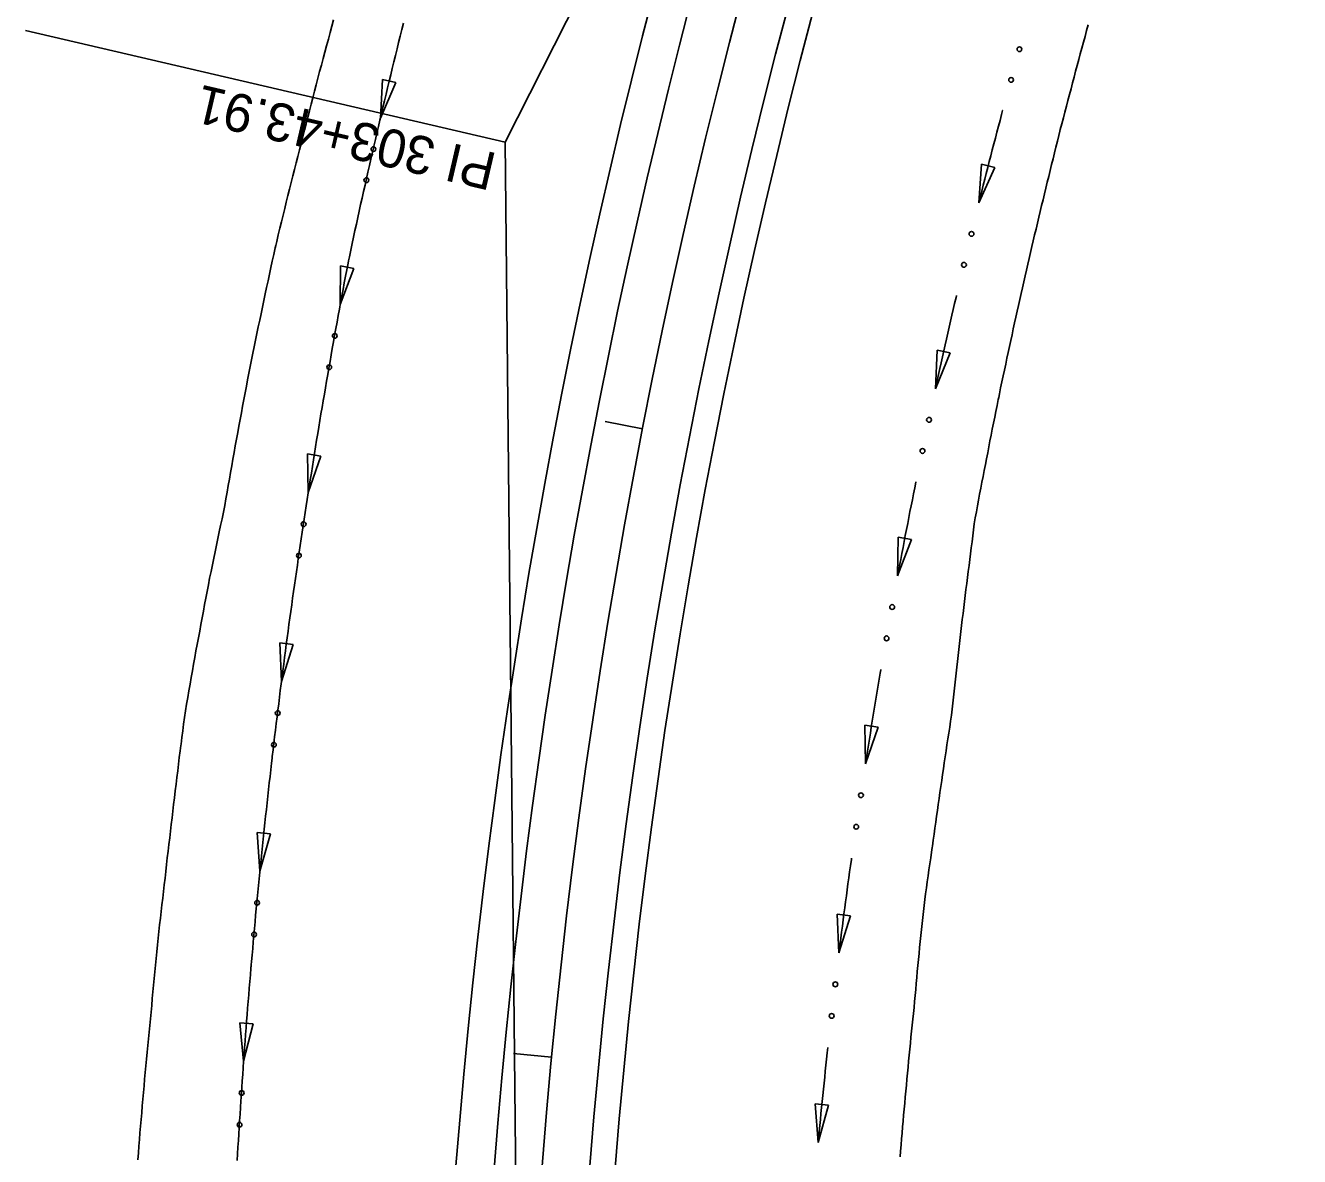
# Model space of a CAD drawing. Extents: x 1611108 to 1749517, y 619561 to 797725.
# Drawn here: x 1713039.8 to 1713240.2, y 759440 to 759618.1 of the extents above; entities that cross this region are included whole.
import ezdxf

# ---------------------------------------------------------------- set-up
doc = ezdxf.new("R2010")
doc.units = 0
for name, color, linetype in [('R_Ditch', 7, 'Continuous'), ('R_Horz Alg', 7, 'Continuous'), ('R_Horz Alg Annot', 7, 'Continuous'), ('R_Horz Alg Stationing', 7, 'Continuous'), ('R_Proposed Const Limits', 7, 'Continuous'), ('R_Proposed Road', 7, 'Continuous'), ('R_Proposed_SHLDR', 7, 'Continuous')]:
    doc.layers.add(name, color=color, linetype=linetype)

msp = doc.modelspace()

# ---------------------------------------------------------------- linework, layer by layer
at = {"layer": 'R_Ditch'}
for p, q in [((1713095.96, 759609.57), (1713095.6, 759603.48)), ((1713095.6, 759603.48), (1713098.02, 759609.08)), ((1713098.02, 759609.08), (1713095.96, 759609.57)), ((1713190.21, 759596.2), (1713189.76, 759590.12)), ((1713192.26, 759595.68), (1713190.21, 759596.2)), ((1713189.76, 759590.12), (1713192.26, 759595.68)), ((1713089.35, 759580.21), (1713089.29, 759574.12)), ((1713091.43, 759579.82), (1713089.35, 759580.21)), ((1713089.29, 759574.12), (1713091.43, 759579.82)), ((1713183.2, 759566.96), (1713182.94, 759560.87)), ((1713182.94, 759560.87), (1713185.26, 759566.5)), ((1713185.26, 759566.5), (1713183.2, 759566.96)), ((1713086.24, 759550.27), (1713084.15, 759550.6)), ((1713084.15, 759550.6), (1713084.25, 759544.51)), ((1713084.25, 759544.51), (1713086.24, 759550.27)), ((1713177.07, 759537.52), (1713176.99, 759531.43)), ((1713176.99, 759531.43), (1713179.15, 759537.13)), ((1713179.15, 759537.13), (1713177.07, 759537.52)), ((1713081.86, 759520.58), (1713079.76, 759520.86)), ((1713079.76, 759520.86), (1713080.04, 759514.77)), ((1713080.04, 759514.77), (1713081.86, 759520.58)), ((1713173.92, 759507.58), (1713171.83, 759507.91)), ((1713171.83, 759507.91), (1713171.93, 759501.82)), ((1713171.93, 759501.82), (1713173.92, 759507.58)), ((1713078.31, 759490.78), (1713076.2, 759491)), ((1713076.2, 759491), (1713076.65, 759484.92)), ((1713076.65, 759484.92), (1713078.31, 759490.78)), ((1713169.57, 759477.89), (1713167.47, 759478.16)), ((1713167.47, 759478.16), (1713167.76, 759472.08)), ((1713167.76, 759472.08), (1713169.57, 759477.89)), ((1713075.58, 759460.9), (1713073.47, 759461.06)), ((1713073.47, 759461.06), (1713074.08, 759455)), ((1713074.08, 759455), (1713075.58, 759460.9)), ((1713166.12, 759448.09), (1713164.01, 759448.29)), ((1713164.01, 759448.29), (1713164.48, 759442.22)), ((1713164.48, 759442.22), (1713166.12, 759448.09))]:
    msp.add_line(p, q, dxfattribs=at)
for points in [[(1713073.08, 759439.36), (1713073.14, 759440.4), (1713073.2, 759441.45), (1713073.26, 759442.49), (1713073.33, 759443.53), (1713073.39, 759444.58), (1713073.46, 759445.62), (1713073.52, 759446.67), (1713073.59, 759447.71), (1713073.66, 759448.76), (1713073.73, 759449.8), (1713073.8, 759450.84), (1713073.87, 759451.89), (1713073.94, 759452.93), (1713074.01, 759453.98), (1713074.09, 759455.02), (1713074.16, 759456.06), (1713074.24, 759457.11), (1713074.32, 759458.15), (1713074.4, 759459.19), (1713074.48, 759460.24), (1713074.56, 759461.28), (1713074.64, 759462.32), (1713074.72, 759463.37), (1713074.8, 759464.41), (1713074.89, 759465.45), (1713074.97, 759466.5), (1713075.06, 759467.54), (1713075.15, 759468.58), (1713075.24, 759469.63), (1713075.33, 759470.67), (1713075.42, 759471.71), (1713075.51, 759472.75), (1713075.6, 759473.8), (1713075.69, 759474.84), (1713075.79, 759475.88), (1713075.88, 759476.93), (1713075.98, 759477.97), (1713076.08, 759479.01), (1713076.18, 759480.05), (1713076.28, 759481.09), (1713076.38, 759482.14), (1713076.48, 759483.18), (1713076.58, 759484.22), (1713076.68, 759485.26), (1713076.79, 759486.3), (1713076.89, 759487.35), (1713077, 759488.39), (1713077.11, 759489.43), (1713077.22, 759490.47), (1713077.33, 759491.51), (1713077.44, 759492.55), (1713077.55, 759493.59), (1713077.66, 759494.64), (1713077.77, 759495.68), (1713077.89, 759496.72), (1713078, 759497.76), (1713078.12, 759498.8), (1713078.24, 759499.84), (1713078.36, 759500.88), (1713078.48, 759501.92), (1713078.57, 759502.73), (1713078.6, 759502.96), (1713078.72, 759504), (1713078.84, 759505.04), (1713078.97, 759506.08), (1713079.09, 759507.12), (1713079.22, 759508.16), (1713079.34, 759509.2), (1713079.47, 759510.24), (1713079.6, 759511.28), (1713079.73, 759512.32), (1713079.86, 759513.36), (1713079.99, 759514.4), (1713080.13, 759515.44), (1713080.26, 759516.48), (1713080.39, 759517.51), (1713080.53, 759518.55), (1713080.67, 759519.59), (1713080.8, 759520.63), (1713080.94, 759521.67), (1713081.08, 759522.71), (1713081.22, 759523.75), (1713081.37, 759524.78), (1713081.51, 759525.82), (1713081.65, 759526.86), (1713081.8, 759527.9), (1713081.94, 759528.93), (1713082.09, 759529.97), (1713082.24, 759531.01), (1713082.39, 759532.05), (1713082.54, 759533.08), (1713082.69, 759534.12), (1713082.84, 759535.16), (1713082.99, 759536.19), (1713083.15, 759537.23), (1713083.3, 759538.27), (1713083.46, 759539.3), (1713083.61, 759540.34), (1713083.77, 759541.38), (1713083.93, 759542.41), (1713084.09, 759543.45), (1713084.25, 759544.48), (1713084.41, 759545.52), (1713084.58, 759546.55), (1713084.74, 759547.59), (1713084.91, 759548.62), (1713085.07, 759549.66), (1713085.24, 759550.69), (1713085.41, 759551.73), (1713085.57, 759552.76), (1713085.74, 759553.8), (1713085.92, 759554.83), (1713086.09, 759555.87), (1713086.26, 759556.9), (1713086.43, 759557.93), (1713086.61, 759558.97), (1713086.79, 759560), (1713086.96, 759561.03), (1713087.14, 759562.07), (1713087.32, 759563.1), (1713087.5, 759564.13), (1713087.68, 759565.17), (1713087.86, 759566.2), (1713088.04, 759567.23), (1713088.23, 759568.26), (1713088.41, 759569.29), (1713088.6, 759570.33), (1713088.79, 759571.36), (1713088.97, 759572.39), (1713089.16, 759573.42), (1713089.35, 759574.45), (1713089.54, 759575.48), (1713089.74, 759576.51), (1713089.93, 759577.55), (1713090.12, 759578.58), (1713090.32, 759579.61), (1713090.51, 759580.64), (1713090.58, 759581.01), (1713090.72, 759581.66), (1713090.94, 759582.69), (1713091.16, 759583.71), (1713091.38, 759584.74), (1713091.61, 759585.76), (1713091.83, 759586.79), (1713092.05, 759587.81), (1713092.28, 759588.84), (1713092.5, 759589.86), (1713092.73, 759590.88), (1713092.96, 759591.91), (1713093.19, 759592.93), (1713093.42, 759593.95), (1713093.65, 759594.98), (1713093.88, 759596), (1713094.11, 759597.02), (1713094.35, 759598.04), (1713094.58, 759599.07), (1713094.82, 759600.09), (1713095.05, 759601.11), (1713095.29, 759602.13), (1713095.53, 759603.15), (1713095.77, 759604.17), (1713096.01, 759605.19), (1713096.25, 759606.21), (1713096.49, 759607.23), (1713096.74, 759608.25), (1713096.98, 759609.27), (1713097.23, 759610.29), (1713097.47, 759611.31), (1713097.72, 759612.33), (1713097.97, 759613.35), (1713098.22, 759614.37), (1713098.47, 759615.39), (1713098.72, 759616.4), (1713098.97, 759617.42), (1713099.23, 759618.44)], [(1713099.13, 759618.06), (1713098.97, 759617.42), (1713098.72, 759616.4), (1713098.47, 759615.39), (1713098.22, 759614.37), (1713097.97, 759613.35), (1713097.72, 759612.33), (1713097.47, 759611.31), (1713097.23, 759610.29), (1713096.98, 759609.27), (1713096.74, 759608.25), (1713096.49, 759607.23), (1713096.25, 759606.21), (1713096.01, 759605.19), (1713095.77, 759604.17), (1713095.61, 759603.48)], [(1713193.51, 759604.65), (1713193.35, 759604.04), (1713193.1, 759603.12), (1713192.86, 759602.19), (1713192.62, 759601.26), (1713192.37, 759600.34), (1713192.13, 759599.41), (1713191.89, 759598.48), (1713191.65, 759597.56), (1713191.41, 759596.63), (1713191.18, 759595.7), (1713190.94, 759594.77), (1713190.71, 759593.85), (1713190.47, 759592.92), (1713190.24, 759591.99), (1713190, 759591.06), (1713189.77, 759590.13), (1713189.77, 759590.12)], [(1713193.52, 759604.69), (1713193.51, 759604.65)], [(1713092.27, 759588.82), (1713092.05, 759587.81), (1713091.83, 759586.79), (1713091.61, 759585.76), (1713091.38, 759584.74), (1713091.16, 759583.71), (1713090.94, 759582.69), (1713090.72, 759581.66), (1713090.58, 759581.01), (1713090.51, 759580.64), (1713090.32, 759579.61), (1713090.12, 759578.58), (1713089.93, 759577.55), (1713089.74, 759576.51), (1713089.54, 759575.48), (1713089.35, 759574.45), (1713089.29, 759574.12)], [(1713092.28, 759588.86), (1713092.28, 759588.84), (1713092.27, 759588.82)], [(1713186.24, 759575.5), (1713186.18, 759575.24), (1713185.96, 759574.3), (1713185.75, 759573.37), (1713185.53, 759572.44), (1713185.32, 759571.5), (1713185.1, 759570.57), (1713184.89, 759569.64), (1713184.68, 759568.7), (1713184.47, 759567.77), (1713184.26, 759566.83), (1713184.05, 759565.9), (1713183.84, 759564.96), (1713183.63, 759564.03), (1713183.43, 759563.09), (1713183.22, 759562.16), (1713183.02, 759561.22), (1713182.94, 759560.87)], [(1713186.25, 759575.54), (1713186.24, 759575.5)], [(1713086.67, 759559.31), (1713086.61, 759558.97), (1713086.43, 759557.93), (1713086.26, 759556.9), (1713086.09, 759555.87), (1713085.92, 759554.83), (1713085.74, 759553.8), (1713085.57, 759552.76), (1713085.41, 759551.73), (1713085.24, 759550.69), (1713085.07, 759549.66), (1713084.91, 759548.62), (1713084.74, 759547.59), (1713084.58, 759546.55), (1713084.41, 759545.52), (1713084.26, 759544.51)], [(1713086.67, 759559.35), (1713086.67, 759559.31)], [(1713179.86, 759546.15), (1713179.68, 759545.28), (1713179.49, 759544.34), (1713179.31, 759543.4), (1713179.12, 759542.46), (1713178.93, 759541.52), (1713178.75, 759540.58), (1713178.57, 759539.64), (1713178.38, 759538.7), (1713178.2, 759537.76), (1713178.02, 759536.82), (1713177.84, 759535.88), (1713177.66, 759534.94), (1713177.48, 759534), (1713177.3, 759533.06), (1713177.13, 759532.12), (1713177, 759531.43)], [(1713179.86, 759546.19), (1713179.86, 759546.15)], [(1713082.04, 759529.63), (1713081.94, 759528.93), (1713081.8, 759527.9), (1713081.65, 759526.86), (1713081.51, 759525.82), (1713081.37, 759524.78), (1713081.22, 759523.75), (1713081.08, 759522.71), (1713080.94, 759521.67), (1713080.8, 759520.63), (1713080.67, 759519.59), (1713080.53, 759518.55), (1713080.39, 759517.51), (1713080.26, 759516.48), (1713080.13, 759515.44), (1713080.04, 759514.77)], [(1713082.05, 759529.67), (1713082.04, 759529.63)], [(1713174.36, 759516.62), (1713174.26, 759516.08), (1713174.1, 759515.14), (1713173.94, 759514.19), (1713173.78, 759513.25), (1713173.63, 759512.3), (1713173.47, 759511.36), (1713173.31, 759510.41), (1713173.16, 759509.47), (1713173, 759508.52), (1713172.85, 759507.57), (1713172.7, 759506.63), (1713172.55, 759505.68), (1713172.4, 759504.74), (1713172.25, 759503.79), (1713172.1, 759502.84), (1713171.95, 759501.9), (1713171.94, 759501.82)], [(1713174.36, 759516.66), (1713174.36, 759516.63)], [(1713078.24, 759499.88), (1713078.24, 759499.84), (1713078.24, 759499.84)], [(1713078.24, 759499.84), (1713078.12, 759498.8), (1713078, 759497.76), (1713077.89, 759496.72), (1713077.77, 759495.68), (1713077.66, 759494.64), (1713077.55, 759493.59), (1713077.44, 759492.55), (1713077.33, 759491.51), (1713077.22, 759490.47), (1713077.11, 759489.43), (1713077, 759488.39), (1713076.89, 759487.35), (1713076.79, 759486.3), (1713076.68, 759485.26), (1713076.65, 759484.92)], [(1713169.74, 759486.94), (1713169.71, 759486.73), (1713169.58, 759485.78), (1713169.44, 759484.83), (1713169.31, 759483.88), (1713169.18, 759482.93), (1713169.06, 759481.98), (1713168.93, 759481.03), (1713168.8, 759480.08), (1713168.67, 759479.13), (1713168.55, 759478.18), (1713168.42, 759477.23), (1713168.3, 759476.28), (1713168.18, 759475.33), (1713168.06, 759474.38), (1713167.94, 759473.43), (1713167.82, 759472.47), (1713167.77, 759472.08)], [(1713169.74, 759486.98), (1713169.74, 759486.95)], [(1713075.26, 759469.95), (1713075.24, 759469.63), (1713075.15, 759468.58), (1713075.06, 759467.54), (1713074.97, 759466.5), (1713074.89, 759465.45), (1713074.8, 759464.41), (1713074.72, 759463.37), (1713074.64, 759462.32), (1713074.56, 759461.28), (1713074.48, 759460.24), (1713074.4, 759459.19), (1713074.32, 759458.15), (1713074.24, 759457.11), (1713074.16, 759456.06), (1713074.09, 759455.02), (1713074.09, 759455)], [(1713075.27, 759469.99), (1713075.26, 759469.95)], [(1713166.01, 759457.14), (1713165.92, 759456.29), (1713165.82, 759455.34), (1713165.71, 759454.38), (1713165.61, 759453.43), (1713165.51, 759452.48), (1713165.41, 759451.52), (1713165.31, 759450.57), (1713165.21, 759449.62), (1713165.12, 759448.66), (1713165.02, 759447.71), (1713164.93, 759446.75), (1713164.83, 759445.8), (1713164.74, 759444.85), (1713164.65, 759443.89), (1713164.55, 759442.94), (1713164.49, 759442.22)], [(1713166.02, 759457.18), (1713166.01, 759457.14)], [(1713073.12, 759440.03), (1713073.12, 759439.99)]]:
    msp.add_lwpolyline(points, dxfattribs=at)
for centre in [(1713196.16, 759614.32), (1713194.84, 759609.49), (1713094.51, 759598.6), (1713093.4, 759593.71), (1713188.61, 759585.25), (1713187.43, 759580.38), (1713088.43, 759569.19), (1713087.56, 759564.26), (1713181.93, 759555.97), (1713180.9, 759551.07), (1713083.53, 759539.55), (1713082.79, 759534.6), (1713176.13, 759526.5), (1713175.25, 759521.57), (1713079.45, 759509.8), (1713078.85, 759504.82), (1713171.22, 759496.87), (1713170.48, 759491.91), (1713076.2, 759479.94), (1713075.74, 759474.95), (1713167.19, 759467.1), (1713166.61, 759462.13), (1713073.78, 759450), (1713073.45, 759445)]:
    msp.add_circle(centre, 0.375, dxfattribs=at)
at = {"layer": 'R_Horz Alg'}
msp.add_arc((1714159.53, 759356.26), 1041.74, 153.16667, 180.59167, dxfattribs=at)
at = {"layer": 'R_Horz Alg Annot'}
for p, q in [((1713115.22, 759599.68), (1713229.96, 759826.5)), ((1713117.85, 759345.5), (1713115.22, 759599.68))]:
    msp.add_line(p, q, dxfattribs=at)
msp.add_lwpolyline([(1713115.22, 759599.68), (1713039.76, 759617.27)], dxfattribs=at)
at = {"layer": 'R_Horz Alg Stationing'}
for points in [[(1713130.95, 759555.71), (1713136.84, 759554.56)], [(1713116.57, 759456.2), (1713122.54, 759455.63)]]:
    msp.add_lwpolyline(points, dxfattribs=at)
at = {"layer": 'R_Proposed Const Limits'}
for points in [[(1713057.44, 759439.49), (1713057.52, 759440.55), (1713057.61, 759441.6), (1713057.69, 759442.66), (1713057.78, 759443.72), (1713057.87, 759444.78), (1713057.96, 759445.83), (1713058.05, 759446.89), (1713058.14, 759447.95), (1713058.23, 759449.01), (1713058.32, 759450.06), (1713058.42, 759451.12), (1713058.51, 759452.18), (1713058.61, 759453.23), (1713058.71, 759454.29), (1713058.8, 759455.34), (1713058.9, 759456.4), (1713059, 759457.46), (1713059.1, 759458.51), (1713059.21, 759459.57), (1713059.31, 759460.62), (1713059.41, 759461.68), (1713059.52, 759462.74), (1713059.62, 759463.79), (1713059.72, 759464.85), (1713059.82, 759465.9), (1713059.92, 759466.96), (1713060.02, 759468.02), (1713060.12, 759469.07), (1713060.23, 759470.13), (1713060.33, 759471.18), (1713060.44, 759472.24), (1713060.54, 759473.3), (1713060.65, 759474.35), (1713060.76, 759475.41), (1713060.87, 759476.46), (1713060.99, 759477.52), (1713061.11, 759478.57), (1713061.23, 759479.62), (1713061.35, 759480.68), (1713061.47, 759481.73), (1713061.6, 759482.79), (1713061.72, 759483.84), (1713061.85, 759484.89), (1713061.97, 759485.95), (1713062.08, 759487), (1713062.2, 759488.06), (1713062.33, 759489.11), (1713062.45, 759490.16), (1713062.57, 759491.22), (1713062.7, 759492.27), (1713062.82, 759493.32), (1713062.95, 759494.38), (1713063.07, 759495.43), (1713063.2, 759496.48), (1713063.33, 759497.54), (1713063.45, 759498.59), (1713063.58, 759499.64), (1713063.71, 759500.7), (1713063.84, 759501.75), (1713063.97, 759502.8), (1713064.1, 759503.86), (1713064.21, 759504.68), (1713064.24, 759504.91), (1713064.37, 759505.96), (1713064.51, 759507.01), (1713064.64, 759508.07), (1713064.78, 759509.12), (1713064.93, 759510.17), (1713065.11, 759511.22), (1713065.29, 759512.26), (1713065.47, 759513.31), (1713065.66, 759514.35), (1713065.84, 759515.4), (1713066.03, 759516.44), (1713066.22, 759517.49), (1713066.4, 759518.53), (1713066.59, 759519.58), (1713066.78, 759520.62), (1713066.97, 759521.66), (1713067.17, 759522.71), (1713067.36, 759523.75), (1713067.55, 759524.79), (1713067.75, 759525.84), (1713067.95, 759526.88), (1713068.14, 759527.92), (1713068.34, 759528.97), (1713068.54, 759530.01), (1713068.74, 759531.05), (1713068.96, 759532.09), (1713069.17, 759533.13), (1713069.38, 759534.17), (1713069.6, 759535.21), (1713069.82, 759536.25), (1713070.03, 759537.28), (1713070.25, 759538.32), (1713070.47, 759539.36), (1713070.69, 759540.4), (1713070.91, 759541.44), (1713071.12, 759542.48), (1713071.3, 759543.52), (1713071.48, 759544.57), (1713071.67, 759545.61), (1713071.85, 759546.65), (1713072.03, 759547.7), (1713072.22, 759548.74), (1713072.4, 759549.78), (1713072.59, 759550.83), (1713072.78, 759551.87), (1713072.97, 759552.91), (1713073.16, 759553.96), (1713073.35, 759555), (1713073.55, 759556.04), (1713073.74, 759557.08), (1713073.93, 759558.13), (1713074.13, 759559.17), (1713074.33, 759560.21), (1713074.52, 759561.25), (1713074.72, 759562.29), (1713074.92, 759563.33), (1713075.13, 759564.37), (1713075.34, 759565.41), (1713075.55, 759566.45), (1713075.76, 759567.49), (1713075.97, 759568.53), (1713076.19, 759569.57), (1713076.4, 759570.6), (1713076.62, 759571.64), (1713076.83, 759572.68), (1713077.05, 759573.72), (1713077.27, 759574.75), (1713077.49, 759575.79), (1713077.71, 759576.83), (1713077.93, 759577.86), (1713078.15, 759578.9), (1713078.37, 759579.94), (1713078.6, 759580.97), (1713078.82, 759582.01), (1713079.05, 759583.04), (1713079.13, 759583.42), (1713079.29, 759584.07), (1713079.54, 759585.11), (1713079.79, 759586.14), (1713080.04, 759587.17), (1713080.3, 759588.19), (1713080.55, 759589.22), (1713080.8, 759590.25), (1713081.06, 759591.28), (1713081.32, 759592.31), (1713081.57, 759593.34), (1713081.83, 759594.37), (1713082.09, 759595.39), (1713082.35, 759596.42), (1713082.61, 759597.45), (1713082.88, 759598.48), (1713083.14, 759599.5), (1713083.4, 759600.53), (1713083.66, 759601.56), (1713083.92, 759602.58), (1713084.18, 759603.61), (1713084.45, 759604.64), (1713084.71, 759605.66), (1713084.98, 759606.69), (1713085.24, 759607.71), (1713085.51, 759608.74), (1713085.78, 759609.76), (1713086.05, 759610.79), (1713086.32, 759611.81), (1713086.59, 759612.84), (1713086.87, 759613.86), (1713087.14, 759614.88), (1713087.42, 759615.9), (1713087.69, 759616.93), (1713087.97, 759617.95), (1713088.25, 759618.97)], [(1713177.37, 759439.92), (1713177.45, 759440.86), (1713177.53, 759441.81), (1713177.61, 759442.75), (1713177.69, 759443.69), (1713177.77, 759444.64), (1713177.85, 759445.58), (1713177.93, 759446.52), (1713178.02, 759447.46), (1713178.1, 759448.41), (1713178.19, 759449.35), (1713178.28, 759450.29), (1713178.36, 759451.23), (1713178.45, 759452.17), (1713178.54, 759453.12), (1713178.63, 759454.06), (1713178.72, 759455), (1713178.81, 759455.94), (1713178.91, 759456.88), (1713179, 759457.83), (1713179.09, 759458.77), (1713179.19, 759459.71), (1713179.29, 759460.65), (1713179.38, 759461.59), (1713179.48, 759462.53), (1713179.58, 759463.47), (1713179.66, 759464.42), (1713179.74, 759465.36), (1713179.83, 759466.3), (1713179.91, 759467.25), (1713180, 759468.19), (1713180.09, 759469.13), (1713180.18, 759470.07), (1713180.27, 759471.02), (1713180.36, 759471.96), (1713180.45, 759472.9), (1713180.54, 759473.84), (1713180.64, 759474.78), (1713180.74, 759475.72), (1713180.85, 759476.67), (1713180.95, 759477.61), (1713181.06, 759478.55), (1713181.17, 759479.49), (1713181.27, 759480.43), (1713181.38, 759481.37), (1713181.51, 759482.31), (1713181.65, 759483.24), (1713181.79, 759484.18), (1713181.92, 759485.12), (1713182.06, 759486.05), (1713182.2, 759486.99), (1713182.34, 759487.93), (1713182.44, 759488.66), (1713182.47, 759488.86), (1713182.6, 759489.8), (1713182.73, 759490.74), (1713182.86, 759491.68), (1713182.99, 759492.61), (1713183.12, 759493.55), (1713183.25, 759494.49), (1713183.38, 759495.43), (1713183.51, 759496.36), (1713183.65, 759497.3), (1713183.78, 759498.24), (1713183.92, 759499.17), (1713184.05, 759500.11), (1713184.19, 759501.05), (1713184.33, 759501.98), (1713184.47, 759502.92), (1713184.61, 759503.86), (1713184.75, 759504.79), (1713184.89, 759505.73), (1713185.03, 759506.66), (1713185.18, 759507.6), (1713185.32, 759508.53), (1713185.47, 759509.47), (1713185.57, 759510.41), (1713185.67, 759511.35), (1713185.77, 759512.3), (1713185.88, 759513.24), (1713185.98, 759514.18), (1713186.08, 759515.12), (1713186.19, 759516.07), (1713186.29, 759517.01), (1713186.4, 759517.95), (1713186.5, 759518.89), (1713186.61, 759519.83), (1713186.72, 759520.78), (1713186.83, 759521.72), (1713186.94, 759522.66), (1713187.05, 759523.6), (1713187.17, 759524.54), (1713187.28, 759525.49), (1713187.39, 759526.43), (1713187.51, 759527.37), (1713187.62, 759528.31), (1713187.74, 759529.25), (1713187.86, 759530.19), (1713187.98, 759531.14), (1713188.1, 759532.08), (1713188.22, 759533.02), (1713188.34, 759533.96), (1713188.46, 759534.9), (1713188.58, 759535.84), (1713188.7, 759536.79), (1713188.81, 759537.73), (1713188.93, 759538.67), (1713189.05, 759539.61), (1713189.21, 759540.55), (1713189.38, 759541.48), (1713189.55, 759542.41), (1713189.72, 759543.35), (1713189.89, 759544.28), (1713190.07, 759545.21), (1713190.25, 759546.14), (1713190.44, 759547.07), (1713190.62, 759548), (1713190.8, 759548.93), (1713190.98, 759549.86), (1713191.16, 759550.79), (1713191.34, 759551.72), (1713191.52, 759552.65), (1713191.7, 759553.58), (1713191.89, 759554.52), (1713192.07, 759555.45), (1713192.26, 759556.38), (1713192.44, 759557.3), (1713192.63, 759558.23), (1713192.82, 759559.16), (1713192.89, 759559.5), (1713193.01, 759560.09), (1713193.2, 759561.02), (1713193.4, 759561.95), (1713193.59, 759562.88), (1713193.79, 759563.8), (1713193.99, 759564.73), (1713194.18, 759565.66), (1713194.38, 759566.59), (1713194.58, 759567.51), (1713194.78, 759568.44), (1713194.99, 759569.37), (1713195.19, 759570.29), (1713195.39, 759571.22), (1713195.6, 759572.14), (1713195.8, 759573.07), (1713196.01, 759574), (1713196.21, 759574.92), (1713196.42, 759575.85), (1713196.63, 759576.77), (1713196.84, 759577.7), (1713197.05, 759578.62), (1713197.26, 759579.55), (1713197.47, 759580.47), (1713197.69, 759581.39), (1713197.9, 759582.32), (1713198.12, 759583.24), (1713198.33, 759584.16), (1713198.55, 759585.09), (1713198.77, 759586.01), (1713198.98, 759586.93), (1713199.2, 759587.86), (1713199.42, 759588.78), (1713199.64, 759589.7), (1713199.87, 759590.62), (1713200.09, 759591.54), (1713200.31, 759592.47), (1713200.54, 759593.39), (1713200.76, 759594.31), (1713200.99, 759595.23), (1713201.22, 759596.15), (1713201.44, 759597.07), (1713201.67, 759597.99), (1713201.9, 759598.91), (1713202.13, 759599.83), (1713202.36, 759600.75), (1713202.53, 759601.4), (1713202.59, 759601.67), (1713202.83, 759602.59), (1713203.07, 759603.51), (1713203.3, 759604.43), (1713203.54, 759605.34), (1713203.78, 759606.26), (1713204.02, 759607.18), (1713204.27, 759608.1), (1713204.51, 759609.01), (1713204.75, 759609.93), (1713204.99, 759610.85), (1713205.24, 759611.76), (1713205.48, 759612.68), (1713205.73, 759613.59), (1713205.98, 759614.51), (1713206.23, 759615.42), (1713206.48, 759616.34), (1713206.73, 759617.25), (1713206.98, 759618.17)]]:
    msp.add_lwpolyline(points, dxfattribs=at)
at = {"layer": 'R_Proposed Road'}
for radius, end in [(1049.24, 178.28394), (1034.24, 180.59167)]:
    msp.add_arc((1714159.53, 759356.26), radius, 153.16667, end, dxfattribs=at)
at = {"layer": 'R_Proposed_SHLDR'}
for radius, end in [(1055.24, 178.28394), (1030.24, 180.59167)]:
    msp.add_arc((1714159.53, 759356.26), radius, 153.16667, end, dxfattribs=at)

# ---------------------------------------------------------------- texts
at = {"layer": 'R_Horz Alg Annot'}
msp.add_text('PI 303+43.91', height=6, rotation=166.8792, dxfattribs=at).set_placement((1713114.18, 759597.87))

doc.saveas('drawing.dxf')
